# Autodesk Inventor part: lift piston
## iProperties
Author: vincent molino
Shininess: 41.0
Angle Display Precision: 2
Document Length Units: 11272
Document Angle Units: 11286
Document Time Units: 11279
Document Mass Units: 11290
Document Length Units Precision: 3
Document Angle Units Precision: 2
Compacted: True
PropertySet Name: _Private Model Information
Created: 2002-01
Part Number: lift piston
Document SubType Name: Modeling
Designer: vincent molino
Control State: 0
Master: False
Checked Out: False
PropertySet Name: Design Tracking Control
Density: 0.0
Volumn: 0.0
Area: 0.0
PropertySet Name: Model Information
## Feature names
1. Extrusion1
2. Extrusion2
